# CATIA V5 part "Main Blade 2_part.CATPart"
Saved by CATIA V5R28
Part number: Main Blade 2_part
Definition: design
Nomenclature: Main Blade 2_part
Source: Unknown
Bounding box of the stored display mesh (mm): x 2.06 to 5.475, y -9.404 to 3.212, z 1.529 to 7.748
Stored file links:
  D:\paraturbo-cad\STEP\Turbocompressor_for_Christophe\Main Blade 2_part.CATPart
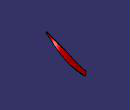
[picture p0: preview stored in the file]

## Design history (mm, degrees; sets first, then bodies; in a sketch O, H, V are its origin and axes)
Body1 "MANIFOLD_SOLID_BREP #34145" (main body)
  Solid1: solid without history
